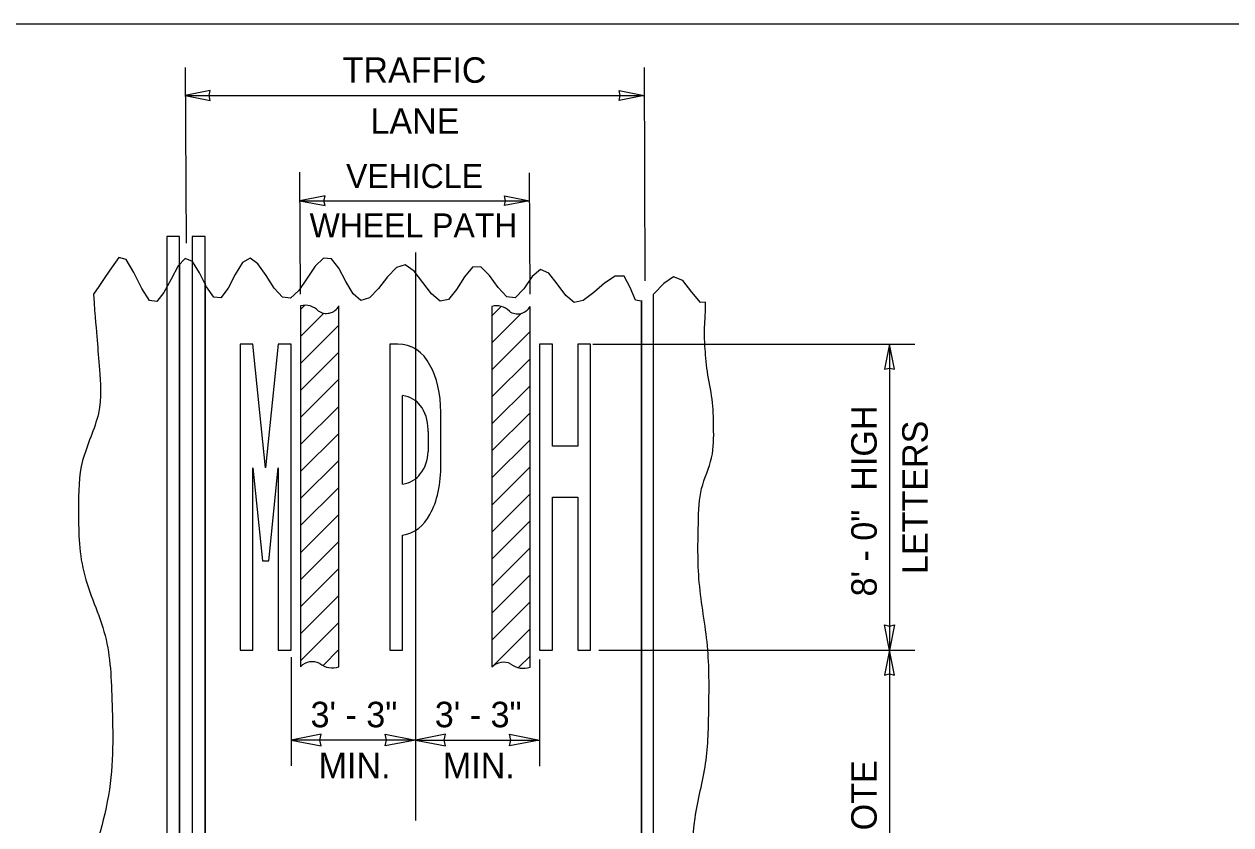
# Model space of a CAD drawing. Extents: x 99862 to 103151, y 100000 to 105076.
# Drawn here: x 101341 to 102098, y 101573 to 102076 of the extents above; entities that cross this region are included whole.
import ezdxf

# ---------------------------------------------------------------- set-up
doc = ezdxf.new("R2010")
doc.units = 0
for name, color, linetype in [('Level 1', 7, 'Continuous'), ('Level 15', 7, 'Continuous'), ('Level 2', 7, 'Continuous'), ('Level 20', 7, 'Continuous'), ('Level 6', 7, 'Continuous'), ('Level 7', 7, 'Continuous'), ('Level 8', 7, 'Continuous')]:
    doc.layers.add(name, color=color, linetype=linetype)

msp = doc.modelspace()

# ---------------------------------------------------------------- linework, layer by layer
at = {"layer": 'Level 1'}
msp.add_lwpolyline([(99862, 99999.5), (103151, 99999.5), (103151, 102075.5), (99862, 102075.5)], close=True, dxfattribs=at)
at = {"layer": 'Level 15'}
for p, q in [((101441.67, 102048.36), (101442.23, 101938.01)), ((101729.67, 102048.36), (101730.21, 101914.41)), ((101441.67, 102030.66), (101729.67, 102030.66)), ((101514.08, 101905.89), (101513.67, 101982.66)), ((101658.08, 101905.89), (101657.67, 101982.16)), ((101513.67, 101964.66), (101657.67, 101964.66)), ((101586.08, 101932.09), (101586.08, 101575.47)), ((101574.08, 101874.57), (101570.08, 101874.57)), ((101570.08, 101874.57), (101570.08, 101682.57)), ((101575.09, 101874.57), (101574.08, 101874.57)), ((101697.58, 101874.57), (101899.69, 101874.57)), ((101883.69, 101874.57), (101883.69, 101682.57)), ((101578.08, 101786.79), (101578.08, 101842.34)), ((101602.07, 101799.2), (101602.08, 101831.79)), ((101594.08, 101819.7), (101594.08, 101807.14)), ((101578.08, 101682.57), (101578.08, 101754.73)), ((101570.08, 101682.57), (101578.08, 101682.57)), ((101701.23, 101682.57), (101899.69, 101682.57)), ((101883.69, 101682.57), (101883.69, 101437.57)), ((101508.08, 101678.07), (101508.08, 101609.91)), ((101664.08, 101676.57), (101664.08, 101609.74)), ((101586.08, 101626.07), (101508.08, 101626.07)), ((101586.08, 101626.07), (101664.08, 101626.07))]:
    msp.add_line(p, q, dxfattribs=at)
for points in [[(101441.67, 102030.66), (101457.39, 102027.58), (101456.66, 102030.66), (101457.39, 102033.74)], [(101729.67, 102030.66), (101713.94, 102027.58), (101714.67, 102030.66), (101713.94, 102033.74)], [(101513.67, 101964.66), (101529.39, 101961.58), (101528.66, 101964.66), (101529.39, 101967.74)], [(101657.67, 101964.66), (101641.94, 101961.58), (101642.67, 101964.66), (101641.94, 101967.74)], [(101500.08, 101796.86), (101500.08, 101682.57), (101508.08, 101682.57), (101508.08, 101874.57), (101500.08, 101874.57), (101492.08, 101796.86), (101484.08, 101874.57), (101476.08, 101874.57), (101476.08, 101682.57), (101484.08, 101682.57), (101484.08, 101796.86), (101490.08, 101738.57), (101494.08, 101738.57)], [(101688.08, 101810.57), (101672.08, 101810.57), (101672.08, 101874.57), (101664.08, 101874.57), (101664.08, 101682.57), (101672.08, 101682.57), (101672.08, 101778.57), (101688.08, 101778.57), (101688.08, 101682.57), (101696.08, 101682.57), (101696.08, 101874.57), (101688.08, 101874.57)], [(101883.69, 101874.57), (101880.6, 101858.85), (101883.69, 101859.58), (101886.77, 101858.85)], [(101883.69, 101682.57), (101880.6, 101698.3), (101883.69, 101697.57), (101886.77, 101698.3)], [(101883.69, 101682.57), (101880.6, 101666.85), (101883.69, 101667.58), (101886.77, 101666.85)], [(101508.08, 101626.07), (101526.95, 101622.37), (101526.07, 101626.07), (101526.95, 101629.77)], [(101586.08, 101626.07), (101567.21, 101622.37), (101568.08, 101626.07), (101567.21, 101629.77)], [(101586.08, 101626.07), (101604.95, 101622.37), (101604.07, 101626.07), (101604.95, 101629.77)], [(101664.08, 101626.07), (101645.21, 101622.37), (101646.08, 101626.07), (101645.21, 101629.77)]]:
    msp.add_lwpolyline(points, close=True, dxfattribs=at)
for centre, radius, start, end in [((101517.08, 101887.91), 11.08, 43.78112, 105.70864), ((101530.27, 101902.73), 8.84, 234.02996, 331.95927), ((101637.08, 101887.61), 11.08, 43.78112, 105.70864), ((101650.27, 101902.43), 8.84, 234.02996, 331.95927), ((101521.41, 101665.07), 10.14, 62.59242, 136.33222), ((101533.91, 101684.07), 12.7, 231.92722, 289.14814), ((101641.41, 101664.78), 10.14, 62.59242, 136.33222), ((101653.91, 101683.78), 12.7, 231.92722, 289.14814)]:
    msp.add_arc(centre, radius, start, end, dxfattribs=at)
for centre, major_axis, ratio, start_param, end_param in [((101575.46, 101848.91), (0, -25.66), 0.883106, 2.078693, 3.158066), ((101583.07, 101831.24), (0, -39.3), 0.483719, 1.584917, 2.445445), ((101575.15, 101829.81), (16.07, 0), 0.792657, 0.505828, 1.38755), ((101580.51, 101820.92), (0, -19.64), 0.691027, 1.570796, 2.445559), ((101580.51, 101820.92), (0, -19.64), 0.691027, 1.529951, 1.570796), ((101580.5, 101820.06), (1.23, -19.57), 0.691023, 1.508615, 1.52981), ((101580.59, 101808.19), (-0.06, -19.57), 0.690438, 0.696034, 1.518966), ((101583.08, 101797.89), (0, -39.31), 0.483307, 0.696034, 1.604189), ((101575.15, 101799.32), (16.07, 0), 0.793333, 4.895635, 5.777357), ((101575.58, 101780.07), (0, -25.5), 0.882353, 0.111341, 1.064968)]:
    msp.add_ellipse(centre, major_axis=major_axis, ratio=ratio, start_param=start_param, end_param=end_param, dxfattribs=at)
at = {"layer": 'Level 2'}
for points in [[(101430.08, 101942.07), (101430.08, 101124.28), (101438.08, 101124.28), (101438.08, 101925.02)], [(101438.08, 101942.07), (101430.08, 101942.07)], [(101430.08, 101942.07), (101430.08, 101124.28), (101438.08, 101124.28)], [(101438.08, 101124.28), (101438.08, 101942.07)], [(101446.08, 101926.55), (101446.08, 101124.28), (101454.08, 101124.28), (101454.08, 101942.07)], [(101454.08, 101942.07), (101446.08, 101942.07)], [(101446.08, 101942.07), (101446.08, 101124.28), (101454.08, 101124.28)], [(101454.08, 101124.28), (101454.08, 101942.07)]]:
    msp.add_lwpolyline(points, dxfattribs=at)
at = {"layer": 'Level 6'}
for p, q in [((101514.08, 101896.41), (101516.6, 101898.93)), ((101514.08, 101879.44), (101528.74, 101894.1)), ((101634.08, 101892.38), (101639.94, 101898.25)), ((101634.08, 101875.41), (101652.72, 101894.06)), ((101514.08, 101862.47), (101538.08, 101886.47)), ((101634.08, 101858.44), (101658.08, 101882.44)), ((101514.08, 101845.5), (101538.08, 101869.5)), ((101634.08, 101841.47), (101658.08, 101865.47)), ((101514.08, 101828.52), (101538.08, 101852.52)), ((101634.08, 101824.5), (101658.08, 101848.5)), ((101514.08, 101811.55), (101538.08, 101835.55)), ((101634.08, 101807.53), (101658.08, 101831.53)), ((101514.08, 101794.58), (101538.08, 101818.58)), ((101634.08, 101790.56), (101658.08, 101814.56)), ((101514.08, 101777.61), (101538.08, 101801.61)), ((101634.08, 101773.59), (101658.08, 101797.59)), ((101514.08, 101760.64), (101538.08, 101784.64)), ((101634.08, 101756.62), (101658.08, 101780.62)), ((101514.08, 101743.67), (101538.08, 101767.67)), ((101634.08, 101739.65), (101658.08, 101763.65)), ((101514.08, 101726.7), (101538.08, 101750.7)), ((101634.08, 101722.68), (101658.08, 101746.68)), ((101514.08, 101709.73), (101538.08, 101733.73)), ((101634.08, 101705.71), (101658.08, 101729.71)), ((101514.08, 101692.76), (101538.08, 101716.76)), ((101634.08, 101688.74), (101658.08, 101712.74)), ((101514.08, 101675.79), (101538.08, 101699.79)), ((101634.12, 101671.81), (101658.08, 101695.77)), ((101528.13, 101672.88), (101538.08, 101682.82)), ((101650.85, 101671.57), (101658.08, 101678.8))]:
    msp.add_line(p, q, dxfattribs=at)
for points in [[(101438.08, 101924.96), (101438.08, 101172.85)], [(101446.08, 101926.89), (101446.08, 101161.96)], [(101430.08, 101910.68), (101430.08, 101168.07)], [(101454.08, 101912.78), (101454.08, 101144.6)], [(101727.94, 101901.92), (101727.94, 101144.31)], [(101735.41, 101905.66), (101735.41, 101159.65)], [(101514.08, 101898.57), (101514.08, 101672.07)], [(101538.08, 101672.07), (101538.08, 101898.57)], [(101634.08, 101898.28), (101634.08, 101671.78)], [(101658.08, 101671.78), (101658.08, 101898.28)]]:
    msp.add_lwpolyline(points, dxfattribs=at)
at = {"layer": 'Level 7'}
for points in [[(101727.94, 101901.52), (101724.35, 101902.14), (101720.82, 101910.07), (101717.15, 101917.34), (101711.49, 101917.37), (101704.9, 101912.96), (101698.03, 101906.97), (101691.46, 101902.02), (101685.75, 101900.77), (101680.47, 101905.05), (101675.2, 101912.36), (101669.93, 101919.08), (101664.65, 101921.55), (101659.38, 101917.14), (101654.11, 101909.42), (101648.83, 101903.59), (101643.53, 101904.21), (101638.11, 101910.2), (101632.64, 101917.78), (101627.21, 101923.2), (101621.92, 101922.88), (101616.9, 101916.91), (101611.97, 101908.89), (101606.95, 101902.6), (101601.66, 101901.63), (101596.24, 101906.17), (101590.78, 101913.38), (101585.29, 101920.4), (101579.79, 101924.35), (101574.26, 101922.8), (101568.63, 101916.91), (101562.98, 101909.55), (101557.4, 101903.6), (101551.96, 101901.93), (101547.01, 101906.15), (101542.49, 101913.94), (101538.08, 101922.26), (101533.47, 101928.12), (101528.43, 101928.6), (101523.28, 101923.65), (101518.12, 101915.95), (101512.95, 101908.3), (101507.8, 101903.46), (101502.67, 101904.08), (101497.51, 101909.81), (101492.37, 101917.77), (101487.3, 101925), (101482.35, 101928.56), (101477.58, 101925.81), (101472.98, 101918.28), (101468.49, 101909.69), (101464.03, 101903.76), (101459.56, 101904.06), (101455.09, 101910.49), (101450.62, 101919.29), (101446.14, 101926.54), (101441.67, 101928.36), (101437.19, 101923.69), (101432.72, 101915.49), (101428.24, 101906.97), (101423.77, 101901.35), (101419.23, 101901.97), (101414.38, 101909.52), (101409.41, 101919.66), (101404.54, 101927.73), (101399.98, 101929.06), (101395.77, 101923.18), (101391.56, 101917.02), (101387.36, 101910.86), (101383.96, 101905.88)], [(101768.27, 101900.85), (101765.15, 101900.83), (101759.65, 101907.22), (101753.97, 101914.5), (101748.09, 101916.75), (101741.99, 101912.63), (101735.82, 101906.12), (101735.41, 101905.79)], [(101727.94, 101149.31), (101727.94, 101901.52)], [(101735.41, 101905.79), (101735.41, 101159.65)]]:
    msp.add_lwpolyline(points, dxfattribs=at)
for points in [[(101383.96, 101905.88), (101385.19, 101890.86), (101386.42, 101875.85), (101387.65, 101860.83), (101390.09, 101831.02), (101374.7, 101801.58), (101374.68, 101772.03), (101374.65, 101731.69), (101394.4, 101691.64), (101395.63, 101651.3), (101397.46, 101591.39), (101375.04, 101530.24), (101377.67, 101470.21), (101378.62, 101448.58), (101390.21, 101427.55), (101390.14, 101405.85), (101390.03, 101369.53), (101379.56, 101333.12), (101380.41, 101296.59), (101381.06, 101268.99), (101382.97, 101241.39), (101383.66, 101213.78), (101384.03, 101198.66), (101383.43, 101183.51), (101383.66, 101168.38), (101383.87, 101162.4), (101387.3, 101148.76), (101392.89, 101135.47), (101401.51, 101114.93), (101433.26, 101189.38), (101441.85, 101169.9), (101445.16, 101162.39), (101446.54, 101161.91), (101449.81, 101154.21), (101451.67, 101149.84), (101453.51, 101145.48), (101456, 101141.46), (101464.99, 101126.87), (101481.78, 101171.88), (101491.67, 101170.37), (101499.29, 101169.21), (101501.46, 101143.83), (101510.37, 101143.45), (101521.29, 101142.99), (101532.79, 101170.16), (101544.55, 101164.16), (101555.64, 101169.6), (101567.42, 101147.01), (101578.22, 101146.95), (101587.63, 101146.89), (101595.98, 101169.18), (101603.92, 101169.38), (101611.55, 101169.56), (101618.29, 101146.35), (101625.87, 101145.95), (101634.04, 101145.51), (101643.36, 101170.85), (101651.56, 101170.37), (101659.3, 101169.93), (101664.38, 101151.6), (101671.76, 101150.95), (101680.02, 101150.22), (101692.18, 101170.61), (101700.45, 101169.88), (101707.95, 101169.21), (101711.86, 101149.72), (101719.16, 101142.95), (101721.85, 101142.67), (101724.84, 101145.44), (101727.94, 101149.31)], [(101735.41, 101159.65), (101738.16, 101162.92), (101740.85, 101165.22), (101743.34, 101165.22), (101751.07, 101165.22), (101758.58, 101124.56), (101761.8, 101137.8), (101768.6, 101157.78), (101766.92, 101186.12), (101765.55, 101214.11), (101764.11, 101243.21), (101757.56, 101272.35), (101756.81, 101301.41), (101755.54, 101351.06), (101776.18, 101400.61), (101775.77, 101450.08), (101775.52, 101481.16), (101759.56, 101511.76), (101759.81, 101542.87), (101760.08, 101577.01), (101769.79, 101611.33), (101770.28, 101645.64), (101770.86, 101685.14), (101762.81, 101724.95), (101763.8, 101764.38), (101764.29, 101783.99), (101773.63, 101803.19), (101773.28, 101822.75), (101772.97, 101840), (101768.88, 101857.33), (101767.79, 101874.63), (101767.24, 101883.33), (101768.12, 101892.09), (101768.27, 101900.85)]]:
    msp.add_open_spline(points, degree=3, dxfattribs=at)
at = {"layer": 'Level 8'}
for points in [[(101494.08, 101738.57), (101500.08, 101796.86), (101500.08, 101682.57), (101508.08, 101682.57), (101508.08, 101874.57), (101500.08, 101874.57), (101492.08, 101796.86), (101484.08, 101874.57), (101476.08, 101874.57), (101476.08, 101682.57), (101484.08, 101682.57), (101484.08, 101796.86), (101490.08, 101738.57), (101494.08, 101738.57)], [(101490.08, 101738.57), (101494.08, 101738.57), (101500.08, 101796.86), (101500.08, 101682.57), (101508.08, 101682.57), (101508.08, 101874.57), (101500.08, 101874.57), (101492.08, 101796.86), (101484.08, 101874.57), (101476.08, 101874.57), (101476.08, 101682.57), (101484.08, 101682.57), (101484.08, 101796.86), (101490.08, 101738.57)], [(101575.09, 101874.57), (101574.08, 101874.57), (101570.08, 101874.57), (101570.08, 101682.57), (101578.08, 101682.57), (101578.08, 101754.73)], [(101575.09, 101874.57), (101574.08, 101874.57), (101570.08, 101874.57), (101570.08, 101682.57), (101578.08, 101682.57), (101578.08, 101754.73)], [(101688.08, 101874.57), (101688.08, 101810.57), (101672.08, 101810.57), (101672.08, 101874.57), (101664.08, 101874.57), (101664.08, 101682.57), (101672.08, 101682.57), (101672.08, 101778.57), (101688.08, 101778.57), (101688.08, 101682.57), (101696.08, 101682.57), (101696.08, 101874.57), (101688.08, 101874.57)], [(101696.08, 101874.57), (101688.08, 101874.57), (101688.08, 101810.57), (101672.08, 101810.57), (101672.08, 101874.57), (101664.08, 101874.57), (101664.08, 101682.57), (101672.08, 101682.57), (101672.08, 101778.57), (101688.08, 101778.57), (101688.08, 101682.57), (101696.08, 101682.57), (101696.08, 101874.57)], [(101578.08, 101786.79), (101578.08, 101842.34)], [(101578.08, 101786.79), (101578.08, 101842.34)], [(101602.07, 101799.2), (101602.08, 101831.79)], [(101602.07, 101799.2), (101602.08, 101831.79)], [(101594.08, 101819.7), (101594.08, 101807.14)], [(101594.08, 101819.7), (101594.08, 101807.14)]]:
    msp.add_lwpolyline(points, dxfattribs=at)
for centre, major_axis, ratio, start_param, end_param in [((101575.46, 101848.91), (0, -25.66), 0.883106, 2.078693, 3.158066), ((101575.46, 101848.91), (0, -25.66), 0.883106, 2.078693, 3.158066), ((101583.07, 101831.24), (0, -39.3), 0.483719, 1.584917, 2.445445), ((101583.07, 101831.24), (0, -39.3), 0.483719, 1.584917, 2.445445), ((101575.15, 101829.81), (16.07, 0), 0.792657, 0.505828, 1.38755), ((101575.15, 101829.81), (16.07, 0), 0.792657, 0.505828, 1.38755), ((101580.51, 101820.92), (0, -19.64), 0.691027, 1.570796, 2.445559), ((101580.51, 101820.92), (0, -19.64), 0.691027, 1.570796, 2.445559), ((101580.51, 101820.92), (0, -19.64), 0.691027, 1.529951, 1.570796), ((101580.51, 101820.92), (0, -19.64), 0.691027, 1.529951, 1.570796), ((101580.5, 101820.06), (1.23, -19.57), 0.691023, 1.508615, 1.52981), ((101580.5, 101820.06), (1.23, -19.57), 0.691023, 1.508615, 1.52981), ((101580.59, 101808.19), (-0.06, -19.57), 0.690438, 0.696034, 1.518966), ((101580.59, 101808.19), (-0.06, -19.57), 0.690438, 0.696034, 1.518966), ((101583.08, 101797.89), (0, -39.31), 0.483307, 0.696034, 1.604189), ((101583.08, 101797.89), (0, -39.31), 0.483307, 0.696034, 1.604189), ((101575.15, 101799.32), (16.07, 0), 0.793333, 4.895635, 5.777357), ((101575.15, 101799.32), (16.07, 0), 0.793333, 4.895635, 5.777357), ((101575.58, 101780.07), (0, -25.5), 0.882353, 0.111341, 1.064968), ((101575.58, 101780.07), (0, -25.5), 0.882353, 0.111341, 1.064968)]:
    msp.add_ellipse(centre, major_axis=major_axis, ratio=ratio, start_param=start_param, end_param=end_param, dxfattribs=at)

# ---------------------------------------------------------------- texts
at = {"layer": 'Level 20'}
for s, height, rotation, p in [('TRAFFIC', 16, 360, (101540.4, 102038.66)), ('LANE', 16, 360, (101557.89, 102006.66)), ('VEHICLE', 15, 360, (101542.64, 101972.66)), ('WHEEL PATH', 15, 360, (101519.73, 101941.66)), ('8\' - 0"  HIGH', 16, 90, (101875.69, 101716.2)), ('LETTERS', 16, 90, (101907.69, 101730.27)), ('3\' - 3"', 16, 360, (101520.29, 101634.07)), ('3\' - 3"', 16, 360, (101598.29, 101634.07)), ('MIN.', 16, 360, (101525.35, 101602.07)), ('MIN.', 16, 360, (101603.35, 101602.07)), ('SEE NOTE', 16, 90, (101875.69, 101505.14))]:
    msp.add_text(s, height=height, rotation=rotation, dxfattribs=at).set_placement(p)

doc.saveas('drawing.dxf')
